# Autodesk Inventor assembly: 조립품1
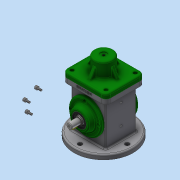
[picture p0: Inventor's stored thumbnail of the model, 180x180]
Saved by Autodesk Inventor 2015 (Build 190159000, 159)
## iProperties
Created: 2018-10
Part Number: 조립품1
Document SubType Name: Assembly
Designer: SCD-A02
Author: SCD-A02
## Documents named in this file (14)
- C:\Users\SCD-A02\Desktop\481007V1018\조립품1.iam
- C:\Users\SCD-A02\Desktop\481007V1018\본체.ipt
- C:\Users\SCD-A02\Desktop\481007V1018\편심축.ipt
- C:\Users\SCD-A02\Desktop\481007V1018\베어링 17 x 40 x 12.ipt
- C:\Users\SCD-A02\Desktop\481007V1018\오일 실 17 30 8.ipt
- C:\Users\SCD-A02\Desktop\481007V1018\키 4 x 4 x 12.ipt
- C:\Users\SCD-A02\Desktop\481007V1018\뒤커버.ipt
- C:\Users\SCD-A02\Desktop\481007V1018\앞커버.ipt
- C:\Users\SCD-A02\Desktop\481007V1018\슬라이더.ipt
- C:\Users\SCD-A02\Desktop\481007V1018\클레비스 핀 6 x 22.ipt
- 클레비스 핀 6 x 22.ipt
- C:\Users\SCD-A02\Desktop\481007V1018\링크.ipt
- C:\Users\SCD-A02\Desktop\481007V1018\덮개.ipt
- C:\Users\SCD-A02\Desktop\481007V1018\볼트 M4 x 8.ipt
